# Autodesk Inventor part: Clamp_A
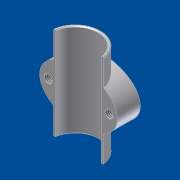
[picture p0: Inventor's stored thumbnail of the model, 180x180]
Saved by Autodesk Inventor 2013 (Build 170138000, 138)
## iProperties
Shininess: 64.0
Length Units: 11269
Angle Units: 11279
Time Units: 11290
Mass Units: 11283
Length Display Precision: 3
Angle Display Precision: 2
Compacted: True
Part Number: Clamp_A
Document SubType Name: Modeling
Created: 2002-10
Designer: roithn
Density: 1 g/cm^3
Material: Generic
Density: 0.0
Volumn: 0.0
Area: 0.0
PropertySet Name: Model Information
Control State: 0
Master: False
Checked Out: False
Author: roithn
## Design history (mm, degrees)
derived "Clamp_top.ipt"
sketch "Sketch1"
  geometry: 5 further points; 2 other entities
  constraints: 8 other
hole "Hole1" sketch "Sketch1" diameter "d8" = 4.917; stored, may be unused: countersink angle "d12" = 82 deg, drill point angle "d14" = 118 deg; dims "d9" = 6, "d10" = 4, "d11" = 2, "d13" = 8
mirror "Mirror1"
body "Solid1"
tag "TaggingFeature3"
feature "DerivedBody::Clamp_top.ipt"
